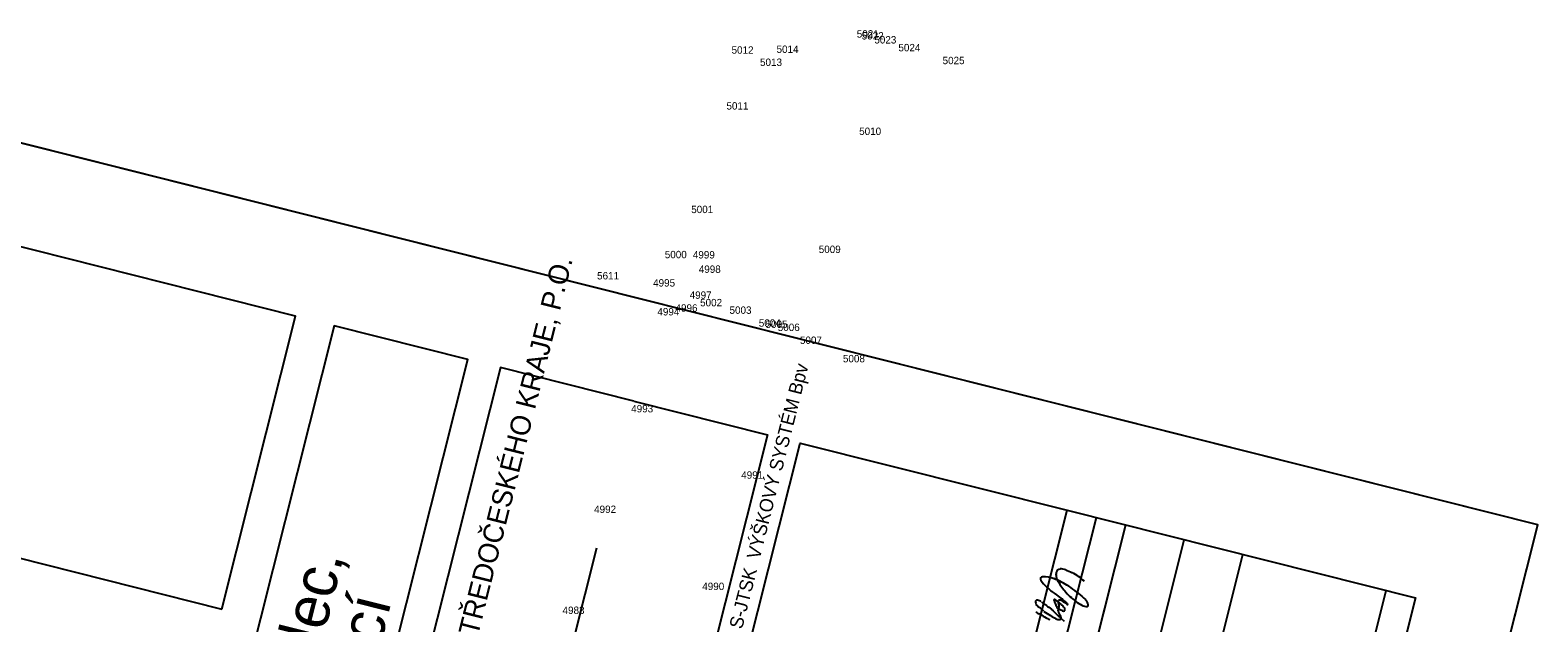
# Model space of a CAD drawing. Extents: x -740053 to -737517, y -1033516 to -1032488.
# Drawn here: x -738977.7 to -738865.5, y -1032946.3 to -1032902.2 of the extents above; entities that cross this region are included whole.
import ezdxf

# ---------------------------------------------------------------- set-up
doc = ezdxf.new("R2010")
doc.units = 0
for name, color, linetype in [('_MIKA', 7, 'Continuous'), ('bod-cislo', 7, 'Continuous'), ('Predmety bez rozlišeni', 7, 'Continuous'), ('promika-formát', 7, 'Continuous'), ('promika-rozp', 7, 'Continuous'), ('promika-rozp-poznamky', 7, 'Continuous'), ('promika-rozp-text-firmy', 7, 'Continuous')]:
    doc.layers.add(name, color=color, linetype=linetype)

msp = doc.modelspace()

# ---------------------------------------------------------------- linework, layer by layer
at = {"layer": '_MIKA'}
msp.add_lwpolyline([(-738900.73, -1032946.2), (-738901.17, -1032945.79)], dxfattribs=at)
for centre, radius, start, end in [((-738901.04, -1032942.6), 0.309, 92.4816, 169.1107), ((-738901.01, -1032943.31), 1.03, 68.3234, 92.4816), ((-738903.34, -1032949.17), 7.32, 64.3201, 68.3234), ((-738902.35, -1032943.03), 0.173, 91.0838, 214.926), ((-738900.14, -1032941.48), 2.87, 214.926, 228.1685), ((-738902.24, -1032944.76), 1.9, 67.2605, 93.4997), ((-738904.48, -1032950.1), 7.7, 58.1131, 67.2605), ((-738900.55, -1032942.69), 0.811, 169.1107, 191.1427), ((-738900.24, -1032942.63), 1.13, 191.1427, 211.3422), ((-738895.75, -1032939.9), 6.38, 211.3422, 220.1693), ((-738903.13, -1032947.93), 5.14, 49.7503, 58.1131), ((-738901.67, -1032945.71), 3.49, 46.0707, 64.3201), ((-738902.41, -1032944.69), 0.474, 175.6936, 219.5783), ((-738902.77, -1032944.72), 0.13, 73.0014, 149.507), ((-738903.02, -1032945.51), 0.96, 53.9936, 73.0014), ((-738897.64, -1032938.7), 6.62, 228.1685, 235.3736), ((-738901.47, -1032944.59), 0.0415, 54.9729, 195.6113), ((-738899.45, -1032944.02), 2.14, 195.6113, 201.6846), ((-738904.97, -1032949.57), 6.13, 53.9935, 54.9729), ((-738905.3, -1032949.79), 6.87, 50.8844, 55.3736), ((-738910.09, -1032956.62), 14.84, 52.0928, 53.9935), ((-738901.01, -1032944.73), 0.188, 163.891, 190.4503), ((-738900.99, -1032944.74), 0.211, 137.3624, 163.891), ((-738901.11, -1032944.91), 0.315, 70.4617, 95.5389), ((-738901.22, -1032945.2), 0.622, 50.9464, 70.4617), ((-739852.09, -1034114.16), 1507.59, 50.87139, 50.88437), ((-738901.55, -1032945.71), 1.33, 37.3071, 50.8714), ((-738898.48, -1032942.2), 2.81, 220.1693, 232.0401), ((-738907.85, -1032954.21), 12.42, 50.0353, 52.0401), ((-738898.44, -1032942.98), 2.23, 230.0353, 243.3172), ((-736558.33, -1030178.1), 3623.91, 229.75034, 229.76132), ((-738899.97, -1032945.28), 1.08, 27.9556, 49.7613), ((-738902.44, -1032945.19), 0.468, 215.0906, 249.0504), ((-738902.11, -1032944.43), 0.869, 219.5783, 234.0124), ((-738905.36, -1032948.92), 4.67, 48.2865, 54.0124), ((-738902.88, -1032946.34), 0.767, 52.9488, 69.0504), ((-738804.05, -1032809.33), 167.38, 233.9936, 234.3077), ((-738892.51, -1032928.29), 20.06, 240.3999, 241.7779), ((-738897.18, -1032938.26), 8.79, 234.7351, 238.5138), ((-738894.01, -1032933.07), 14.87, 238.5138, 240.3031), ((-738886.58, -1032930.09), 21.43, 225.0991, 227.1101), ((-738898.94, -1032943.82), 2.69, 201.6846, 209.0811), ((-738907, -1032948.3), 6.53, 28.3697, 29.0811), ((-738901.14, -1032945.14), 0.128, 208.3697, 235.9466), ((-738901.19, -1032945.21), 0.0443, 235.9466, 346.913), ((-738901.14, -1032945.37), 0.0751, 46.6674, 215.9316), ((-738900.85, -1032944.7), 0.357, 190.4503, 205.7981), ((-738900.1, -1032945.01), 1.17, 199.8625, 209.1509), ((-738901.61, -1032945.07), 0.489, 12.1212, 25.7981), ((-738902.24, -1032944.97), 1.12, 346.913, 352.9911), ((-738901.52, -1032945.05), 0.4, 352.9911, 12.1212), ((-738903.38, -1032946.84), 2.58, 21.1215, 29.1509), ((-738901.8, -1032947.31), 2.12, 64.3119, 70.5602), ((-738750.65, -1032803.1), 206.66, 223.3314, 223.4234), ((-738900.8, -1032945.24), 0.174, 244.3119, 302.5061), ((-738900.39, -1032944.18), 0.693, 230.9464, 242.8233), ((-738900.9, -1032945.3), 0.211, 334.1467, 43.4234), ((-738901.26, -1032945.88), 1.22, 57.0008, 62.8233), ((-738899.94, -1032943.84), 1.22, 237.0008, 242.8233), ((-738900.49, -1032944.91), 0.00871, 242.8233, 88.9163), ((-738899.01, -1032944.19), 0.892, 241.4111, 267.5968), ((-738899.07, -1032944.97), 0.114, 280.4929, 17.2153), ((-738899.57, -1032945.07), 0.623, 11.8949, 27.9556), ((-738900.51, -1032943.19), 3.15, 241.7779, 245.4134), ((-738901.12, -1032945.55), 0.503, 240.3031, 276.1469), ((-738901.08, -1032945.93), 0.115, 276.1469, 11.4898)]:
    msp.add_arc(centre, radius, start, end, dxfattribs=at)
at = {"layer": 'Predmety bez rozlišeni'}
for p, q in [((-738865.49, -1032938.99), (-739009.5, -1032902.74)), ((-738891.12, -1033040.82), (-738865.49, -1032938.99))]:
    msp.add_line(p, q, dxfattribs=at)
at = {"layer": 'promika-formát'}
msp.add_lwpolyline([(-738891.12, -1033040.82), (-738865.49, -1032938.99), (-739009.5, -1032902.74), (-739035.13, -1033004.56)], close=True, dxfattribs=at)
at = {"layer": 'promika-rozp'}
for p, q in [((-738922.51, -1033025.18), (-738900.53, -1032937.9)), ((-738920.32, -1033025.73), (-738898.35, -1032938.45)), ((-738918.14, -1033026.28), (-738896.17, -1032939)), ((-738913.78, -1033027.38), (-738891.81, -1032940.1)), ((-738909.41, -1033028.48), (-738887.44, -1032941.2)), ((-738898.75, -1033031.16), (-738876.78, -1032943.88))]:
    msp.add_line(p, q, dxfattribs=at)
msp.add_lwpolyline([(-738967.11, -1033013.95), (-738945.14, -1032926.67), (-738955.08, -1032924.17), (-738977.05, -1033011.45)], close=True, dxfattribs=at)
for points in [[(-738932.78, -1032929.79), (-738942.72, -1032927.28), (-738964.69, -1033014.56), (-738954.75, -1033017.06)], [(-738932.78, -1032929.79), (-738922.84, -1032932.29), (-738944.81, -1033019.57), (-738954.75, -1033017.06)], [(-738922.51, -1033025.18), (-738942.39, -1033020.18), (-738920.41, -1032932.9), (-738900.53, -1032937.9)], [(-738900.53, -1032937.9), (-738874.59, -1032944.43), (-738896.57, -1033031.71), (-738922.51, -1033025.18)], [(-738918.14, -1033026.28), (-738896.17, -1032939)], [(-738946.9, -1032985.86), (-738935.53, -1032940.7)]]:
    msp.add_lwpolyline(points, dxfattribs=at)
at = {"layer": 'promika-rozp-poznamky'}
msp.add_lwpolyline([(-738963.46, -1032945.27), (-738957.96, -1032923.45), (-738979.78, -1032917.95), (-738985.27, -1032939.77)], close=True, dxfattribs=at)

# ---------------------------------------------------------------- texts
at = {"layer": 'bod-cislo'}
for s, p in [('5021', (-738916.19, -1032902.71)), ('5022', (-738915.82, -1032902.85)), ('5023', (-738914.88, -1032903.15)), ('5012', (-738925.51, -1032903.91)), ('5013', (-738923.39, -1032904.82)), ('5014', (-738922.16, -1032903.85)), ('5024', (-738913.09, -1032903.73)), ('5025', (-738909.8, -1032904.69)), ('5011', (-738925.89, -1032908.07)), ('5010', (-738916.01, -1032909.96)), ('5001', (-738928.51, -1032915.78)), ('5000', (-738930.48, -1032919.14)), ('4999', (-738928.39, -1032919.16)), ('5009', (-738919.02, -1032918.75)), ('4998', (-738927.95, -1032920.23)), ('5611', (-738935.52, -1032920.72)), ('4995', (-738931.35, -1032921.25)), ('4997', (-738928.63, -1032922.16)), ('5002', (-738927.85, -1032922.72)), ('4994', (-738931.03, -1032923.4)), ('4996', (-738929.68, -1032923.12)), ('5003', (-738925.66, -1032923.28)), ('5004', (-738923.48, -1032924.24)), ('5005', (-738922.98, -1032924.33)), ('5006', (-738922.07, -1032924.56)), ('5007', (-738920.42, -1032925.52)), ('5008', (-738917.22, -1032926.89)), ('4993', (-738932.98, -1032930.62)), ('4991', (-738924.79, -1032935.56)), ('4992', (-738935.74, -1032938.11)), ('4990', (-738927.69, -1032943.85)), ('4983', (-738938.09, -1032945.63))]:
    msp.add_text(s, height=0.55, dxfattribs=at).set_placement(p)
at = {"layer": 'promika-rozp'}
msp.add_text('SOUŘADNICOVÝ SYSTÉM S-JTSK  VÝŠKOVÝ SYSTÉM Bpv', height=1, rotation=75.8698, dxfattribs=at).set_placement((-738928.9, -1032963.38))
at = {"layer": 'promika-rozp-text-firmy'}
for s, height, p in [('KRAJSKÁ SPRÁVA A ÚDRŽBA SILNIC STŘEDOČESKÉHO KRAJE, P.O.', 1.5, (-738953.54, -1032983.65)), ('III/0083 a III/0084 Sedlec,', 3.25, (-738966.46, -1032989.37)), ('rekonstrukce komunikací', 3.25, (-738962.54, -1032991.29))]:
    msp.add_text(s, height=height, rotation=75.8698, dxfattribs=at).set_placement(p)

doc.saveas('drawing.dxf')
